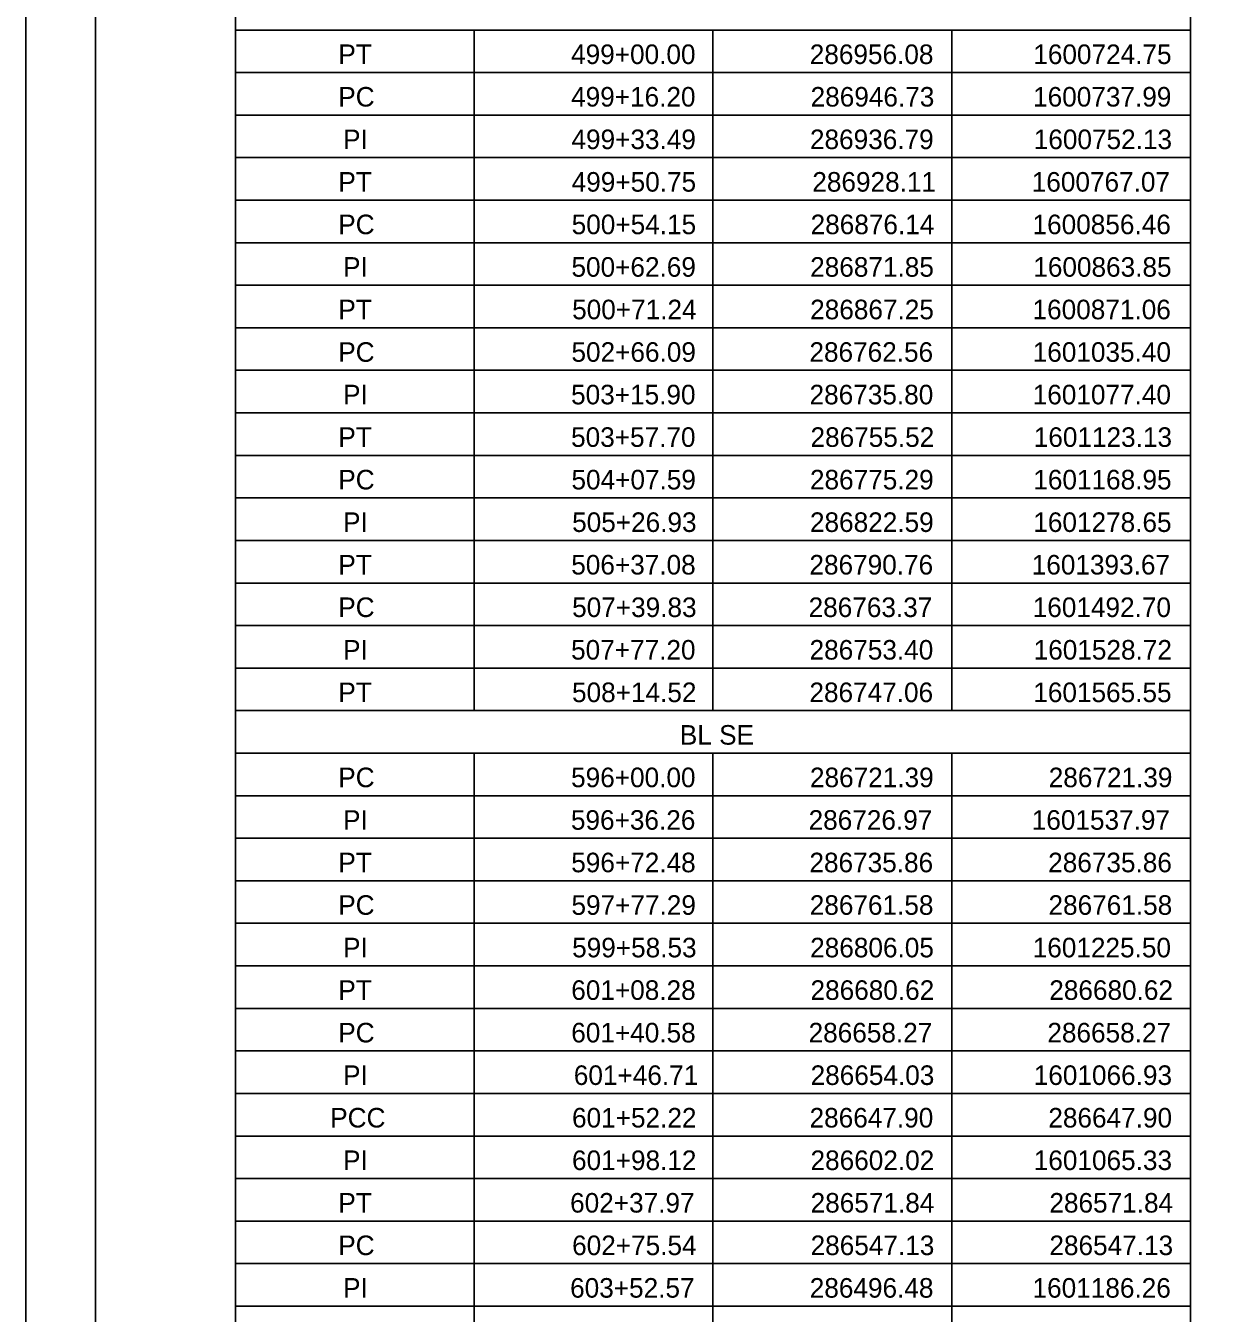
# Model space of a CAD drawing. Extents: x 0 to 34, y 0 to 22.
# Drawn here: x 0 to 8.5, y 7.75 to 16.97 of the extents above; entities that cross this region are included whole.
import ezdxf

# ---------------------------------------------------------------- set-up
doc = ezdxf.new("R2010")
doc.units = 0
for name, color, linetype in [('SH_Border', 7, 'Continuous'), ('SH_Cut_Line', 7, 'Continuous'), ('SH_Text', 7, 'Continuous')]:
    doc.layers.add(name, color=color, linetype=linetype)

msp = doc.modelspace()

# ---------------------------------------------------------------- linework, layer by layer
at = {"layer": 'SH_Border'}
for points in [[(0.5, 21.5), (1.5, 21.5), (1.5, 0.5), (0.5, 0.5)], [(1.5, 21.5), (33.5, 21.5), (33.5, 0.5), (1.5, 0.5)]]:
    msp.add_lwpolyline(points, close=True, dxfattribs=at)
at = {"layer": 'SH_Cut_Line'}
msp.add_lwpolyline([(0, 0), (34, 0), (34, 22), (0, 22)], close=True, dxfattribs=at)
at = {"layer": 'SH_Text'}
for p, q in [((1.5, 17.2391), (1.5, 16.3261)), ((8.3309, 17.2391), (8.3309, 16.3261)), ((1.5, 16.9348), (8.3309, 16.9348)), ((3.2077, 16.9348), (3.2077, 16.3261)), ((4.9155, 16.9348), (4.9155, 16.3261)), ((6.6232, 16.9348), (6.6232, 16.3261)), ((1.5, 16.6304), (8.3309, 16.6304)), ((1.5, 16.3261), (8.3309, 16.3261)), ((1.5, 16.3261), (1.5, 16.0217)), ((3.2077, 16.3261), (3.2077, 16.0217)), ((4.9155, 16.3261), (4.9155, 16.0217)), ((6.6232, 16.3261), (6.6232, 16.0217)), ((8.3309, 16.3261), (8.3309, 16.0217)), ((1.5, 16.0217), (8.3309, 16.0217)), ((1.5, 16.0217), (1.5, 15.413)), ((3.2077, 16.0217), (3.2077, 15.413)), ((4.9155, 16.0217), (4.9155, 15.413)), ((6.6232, 16.0217), (6.6232, 15.413)), ((8.3309, 16.0217), (8.3309, 15.413)), ((1.5, 15.7174), (8.3309, 15.7174)), ((1.5, 15.413), (8.3309, 15.413)), ((1.5, 15.413), (1.5, 15.1087)), ((3.2077, 15.413), (3.2077, 15.1087)), ((4.9155, 15.413), (4.9155, 15.1087)), ((6.6232, 15.413), (6.6232, 15.1087)), ((8.3309, 15.413), (8.3309, 15.1087)), ((1.5, 15.1087), (8.3309, 15.1087)), ((1.5, 15.1087), (1.5, 14.5)), ((3.2077, 15.1087), (3.2077, 14.5)), ((4.9155, 15.1087), (4.9155, 14.5)), ((6.6232, 15.1087), (6.6232, 14.5)), ((8.3309, 15.1087), (8.3309, 14.5)), ((1.5, 14.8043), (8.3309, 14.8043)), ((1.5, 14.5), (8.3309, 14.5)), ((1.5, 14.5), (1.5, 14.1957)), ((3.2077, 14.5), (3.2077, 14.1957)), ((4.9155, 14.5), (4.9155, 14.1957)), ((6.6232, 14.5), (6.6232, 14.1957)), ((8.3309, 14.5), (8.3309, 14.1957)), ((1.5, 14.1957), (8.3309, 14.1957)), ((1.5, 14.1957), (1.5, 13.587)), ((3.2077, 14.1957), (3.2077, 13.587)), ((4.9155, 14.1957), (4.9155, 13.587)), ((6.6232, 14.1957), (6.6232, 13.587)), ((8.3309, 14.1957), (8.3309, 13.587)), ((1.5, 13.8913), (8.3309, 13.8913)), ((1.5, 13.587), (8.3309, 13.587)), ((1.5, 13.587), (1.5, 13.2826)), ((3.2077, 13.587), (3.2077, 13.2826)), ((4.9155, 13.587), (4.9155, 13.2826)), ((6.6232, 13.587), (6.6232, 13.2826)), ((8.3309, 13.587), (8.3309, 13.2826)), ((1.5, 13.2826), (8.3309, 13.2826)), ((1.5, 13.2826), (1.5, 12.6739)), ((3.2077, 13.2826), (3.2077, 12.6739)), ((4.9155, 13.2826), (4.9155, 12.6739)), ((6.6232, 13.2826), (6.6232, 12.6739)), ((8.3309, 13.2826), (8.3309, 12.6739)), ((1.5, 12.9783), (8.3309, 12.9783)), ((1.5, 12.6739), (8.3309, 12.6739)), ((1.5, 12.6739), (1.5, 12.3696)), ((3.2077, 12.6739), (3.2077, 12.3696)), ((4.9155, 12.6739), (4.9155, 12.3696)), ((6.6232, 12.6739), (6.6232, 12.3696)), ((8.3309, 12.6739), (8.3309, 12.3696)), ((1.5, 12.3696), (8.3309, 12.3696)), ((1.5, 12.3696), (1.5, 11.4565)), ((3.2077, 12.3696), (3.2077, 12.0652)), ((4.9155, 12.3696), (4.9155, 12.0652)), ((6.6232, 12.3696), (6.6232, 12.0652)), ((8.3309, 12.3696), (8.3309, 11.4565)), ((1.5, 12.0652), (8.3309, 12.0652)), ((1.5, 11.7609), (8.3309, 11.7609)), ((3.2077, 11.7609), (3.2077, 11.4565)), ((4.9155, 11.7609), (4.9155, 11.4565)), ((6.6232, 11.7609), (6.6232, 11.4565)), ((1.5, 11.4565), (8.3309, 11.4565)), ((1.5, 11.4565), (1.5, 11.1522)), ((3.2077, 11.4565), (3.2077, 11.1522)), ((4.9155, 11.4565), (4.9155, 11.1522)), ((6.6232, 11.4565), (6.6232, 11.1522)), ((8.3309, 11.4565), (8.3309, 11.1522)), ((1.5, 11.1522), (8.3309, 11.1522)), ((1.5, 11.1522), (1.5, 10.5435)), ((3.2077, 11.1522), (3.2077, 10.5435)), ((4.9155, 11.1522), (4.9155, 10.5435)), ((6.6232, 11.1522), (6.6232, 10.5435)), ((8.3309, 11.1522), (8.3309, 10.5435)), ((1.5, 10.8478), (8.3309, 10.8478)), ((1.5, 10.5435), (8.3309, 10.5435)), ((1.5, 10.5435), (1.5, 10.2391)), ((3.2077, 10.5435), (3.2077, 10.2391)), ((4.9155, 10.5435), (4.9155, 10.2391)), ((6.6232, 10.5435), (6.6232, 10.2391)), ((8.3309, 10.5435), (8.3309, 10.2391)), ((1.5, 10.2391), (8.3309, 10.2391)), ((1.5, 10.2391), (1.5, 9.6304)), ((3.2077, 10.2391), (3.2077, 9.6304)), ((4.9155, 10.2391), (4.9155, 9.6304)), ((6.6232, 10.2391), (6.6232, 9.6304)), ((8.3309, 10.2391), (8.3309, 9.6304)), ((1.5, 9.9348), (8.3309, 9.9348)), ((1.5, 9.6304), (8.3309, 9.6304)), ((1.5, 9.6304), (1.5, 9.3261)), ((3.2077, 9.6304), (3.2077, 9.3261)), ((4.9155, 9.6304), (4.9155, 9.3261)), ((6.6232, 9.6304), (6.6232, 9.3261)), ((8.3309, 9.6304), (8.3309, 9.3261)), ((1.5, 9.3261), (8.3309, 9.3261)), ((1.5, 9.3261), (1.5, 9.0217)), ((3.2077, 9.3261), (3.2077, 9.0217)), ((4.9155, 9.3261), (4.9155, 9.0217)), ((6.6232, 9.3261), (6.6232, 9.0217)), ((8.3309, 9.3261), (8.3309, 9.0217)), ((1.5, 9.0217), (8.3309, 9.0217)), ((1.5, 9.0217), (1.5, 8.7174)), ((3.2077, 9.0217), (3.2077, 8.7174)), ((4.9155, 9.0217), (4.9155, 8.7174)), ((6.6232, 9.0217), (6.6232, 8.7174)), ((8.3309, 9.0217), (8.3309, 8.7174)), ((1.5, 8.7174), (8.3309, 8.7174)), ((1.5, 8.7174), (1.5, 8.1087)), ((3.2077, 8.7174), (3.2077, 8.1087)), ((4.9155, 8.7174), (4.9155, 8.1087)), ((6.6232, 8.7174), (6.6232, 8.1087)), ((8.3309, 8.7174), (8.3309, 8.1087)), ((1.5, 8.413), (8.3309, 8.413)), ((1.5, 8.1087), (8.3309, 8.1087)), ((1.5, 8.1087), (1.5, 7.8043)), ((3.2077, 8.1087), (3.2077, 7.8043)), ((4.9155, 8.1087), (4.9155, 7.8043)), ((6.6232, 8.1087), (6.6232, 7.8043)), ((8.3309, 8.1087), (8.3309, 7.8043)), ((1.5, 7.8043), (8.3309, 7.8043)), ((1.5, 7.8043), (1.5, 7.1957)), ((3.2077, 7.8043), (3.2077, 7.1957)), ((4.9155, 7.8043), (4.9155, 7.1957)), ((6.6232, 7.8043), (6.6232, 7.1957)), ((8.3309, 7.8043), (8.3309, 7.1957))]:
    msp.add_line(p, q, dxfattribs=at)
for points in [[(1.5, 16.9348), (3.2077, 16.9348), (3.2077, 16.6304), (1.5, 16.6304)], [(3.2077, 16.9348), (4.9155, 16.9348), (4.9155, 16.6304), (3.2077, 16.6304)], [(4.9155, 16.9348), (6.6232, 16.9348), (6.6232, 16.6304), (4.9155, 16.6304)], [(6.6232, 16.9348), (8.3309, 16.9348), (8.3309, 16.6304), (6.6232, 16.6304)], [(1.5, 16.6304), (3.2077, 16.6304), (3.2077, 16.3261), (1.5, 16.3261)], [(3.2077, 16.6304), (4.9155, 16.6304), (4.9155, 16.3261), (3.2077, 16.3261)], [(4.9155, 16.6304), (6.6232, 16.6304), (6.6232, 16.3261), (4.9155, 16.3261)], [(6.6232, 16.6304), (8.3309, 16.6304), (8.3309, 16.3261), (6.6232, 16.3261)], [(1.5, 16.3261), (3.2077, 16.3261), (3.2077, 16.0217), (1.5, 16.0217)], [(3.2077, 16.3261), (4.9155, 16.3261), (4.9155, 16.0217), (3.2077, 16.0217)], [(4.9155, 16.3261), (6.6232, 16.3261), (6.6232, 16.0217), (4.9155, 16.0217)], [(6.6232, 16.3261), (8.3309, 16.3261), (8.3309, 16.0217), (6.6232, 16.0217)], [(1.5, 16.0217), (3.2077, 16.0217), (3.2077, 15.7174), (1.5, 15.7174)], [(3.2077, 16.0217), (4.9155, 16.0217), (4.9155, 15.7174), (3.2077, 15.7174)], [(4.9155, 16.0217), (6.6232, 16.0217), (6.6232, 15.7174), (4.9155, 15.7174)], [(6.6232, 16.0217), (8.3309, 16.0217), (8.3309, 15.7174), (6.6232, 15.7174)], [(1.5, 15.7174), (3.2077, 15.7174), (3.2077, 15.413), (1.5, 15.413)], [(3.2077, 15.7174), (4.9155, 15.7174), (4.9155, 15.413), (3.2077, 15.413)], [(4.9155, 15.7174), (6.6232, 15.7174), (6.6232, 15.413), (4.9155, 15.413)], [(6.6232, 15.7174), (8.3309, 15.7174), (8.3309, 15.413), (6.6232, 15.413)], [(1.5, 15.413), (3.2077, 15.413), (3.2077, 15.1087), (1.5, 15.1087)], [(3.2077, 15.413), (4.9155, 15.413), (4.9155, 15.1087), (3.2077, 15.1087)], [(4.9155, 15.413), (6.6232, 15.413), (6.6232, 15.1087), (4.9155, 15.1087)], [(6.6232, 15.413), (8.3309, 15.413), (8.3309, 15.1087), (6.6232, 15.1087)], [(1.5, 15.1087), (3.2077, 15.1087), (3.2077, 14.8043), (1.5, 14.8043)], [(3.2077, 15.1087), (4.9155, 15.1087), (4.9155, 14.8043), (3.2077, 14.8043)], [(4.9155, 15.1087), (6.6232, 15.1087), (6.6232, 14.8043), (4.9155, 14.8043)], [(6.6232, 15.1087), (8.3309, 15.1087), (8.3309, 14.8043), (6.6232, 14.8043)], [(1.5, 14.8043), (3.2077, 14.8043), (3.2077, 14.5), (1.5, 14.5)], [(3.2077, 14.8043), (4.9155, 14.8043), (4.9155, 14.5), (3.2077, 14.5)], [(4.9155, 14.8043), (6.6232, 14.8043), (6.6232, 14.5), (4.9155, 14.5)], [(6.6232, 14.8043), (8.3309, 14.8043), (8.3309, 14.5), (6.6232, 14.5)], [(1.5, 14.5), (3.2077, 14.5), (3.2077, 14.1957), (1.5, 14.1957)], [(3.2077, 14.5), (4.9155, 14.5), (4.9155, 14.1957), (3.2077, 14.1957)], [(4.9155, 14.5), (6.6232, 14.5), (6.6232, 14.1957), (4.9155, 14.1957)], [(6.6232, 14.5), (8.3309, 14.5), (8.3309, 14.1957), (6.6232, 14.1957)], [(1.5, 14.1957), (3.2077, 14.1957), (3.2077, 13.8913), (1.5, 13.8913)], [(3.2077, 14.1957), (4.9155, 14.1957), (4.9155, 13.8913), (3.2077, 13.8913)], [(4.9155, 14.1957), (6.6232, 14.1957), (6.6232, 13.8913), (4.9155, 13.8913)], [(6.6232, 14.1957), (8.3309, 14.1957), (8.3309, 13.8913), (6.6232, 13.8913)], [(1.5, 13.8913), (3.2077, 13.8913), (3.2077, 13.587), (1.5, 13.587)], [(3.2077, 13.8913), (4.9155, 13.8913), (4.9155, 13.587), (3.2077, 13.587)], [(4.9155, 13.8913), (6.6232, 13.8913), (6.6232, 13.587), (4.9155, 13.587)], [(6.6232, 13.8913), (8.3309, 13.8913), (8.3309, 13.587), (6.6232, 13.587)], [(1.5, 13.587), (3.2077, 13.587), (3.2077, 13.2826), (1.5, 13.2826)], [(3.2077, 13.587), (4.9155, 13.587), (4.9155, 13.2826), (3.2077, 13.2826)], [(4.9155, 13.587), (6.6232, 13.587), (6.6232, 13.2826), (4.9155, 13.2826)], [(6.6232, 13.587), (8.3309, 13.587), (8.3309, 13.2826), (6.6232, 13.2826)], [(1.5, 13.2826), (3.2077, 13.2826), (3.2077, 12.9783), (1.5, 12.9783)], [(3.2077, 13.2826), (4.9155, 13.2826), (4.9155, 12.9783), (3.2077, 12.9783)], [(4.9155, 13.2826), (6.6232, 13.2826), (6.6232, 12.9783), (4.9155, 12.9783)], [(6.6232, 13.2826), (8.3309, 13.2826), (8.3309, 12.9783), (6.6232, 12.9783)], [(1.5, 12.9783), (3.2077, 12.9783), (3.2077, 12.6739), (1.5, 12.6739)], [(3.2077, 12.9783), (4.9155, 12.9783), (4.9155, 12.6739), (3.2077, 12.6739)], [(4.9155, 12.9783), (6.6232, 12.9783), (6.6232, 12.6739), (4.9155, 12.6739)], [(6.6232, 12.9783), (8.3309, 12.9783), (8.3309, 12.6739), (6.6232, 12.6739)], [(1.5, 12.6739), (3.2077, 12.6739), (3.2077, 12.3696), (1.5, 12.3696)], [(3.2077, 12.6739), (4.9155, 12.6739), (4.9155, 12.3696), (3.2077, 12.3696)], [(4.9155, 12.6739), (6.6232, 12.6739), (6.6232, 12.3696), (4.9155, 12.3696)], [(6.6232, 12.6739), (8.3309, 12.6739), (8.3309, 12.3696), (6.6232, 12.3696)], [(1.5, 12.3696), (3.2077, 12.3696), (3.2077, 12.0652), (1.5, 12.0652)], [(3.2077, 12.3696), (4.9155, 12.3696), (4.9155, 12.0652), (3.2077, 12.0652)], [(4.9155, 12.3696), (6.6232, 12.3696), (6.6232, 12.0652), (4.9155, 12.0652)], [(6.6232, 12.3696), (8.3309, 12.3696), (8.3309, 12.0652), (6.6232, 12.0652)], [(1.5, 11.7609), (3.2077, 11.7609), (3.2077, 11.4565), (1.5, 11.4565)], [(3.2077, 11.7609), (4.9155, 11.7609), (4.9155, 11.4565), (3.2077, 11.4565)], [(4.9155, 11.7609), (6.6232, 11.7609), (6.6232, 11.4565), (4.9155, 11.4565)], [(6.6232, 11.7609), (8.3309, 11.7609), (8.3309, 11.4565), (6.6232, 11.4565)], [(1.5, 11.4565), (3.2077, 11.4565), (3.2077, 11.1522), (1.5, 11.1522)], [(3.2077, 11.4565), (4.9155, 11.4565), (4.9155, 11.1522), (3.2077, 11.1522)], [(4.9155, 11.4565), (6.6232, 11.4565), (6.6232, 11.1522), (4.9155, 11.1522)], [(6.6232, 11.4565), (8.3309, 11.4565), (8.3309, 11.1522), (6.6232, 11.1522)], [(1.5, 11.1522), (3.2077, 11.1522), (3.2077, 10.8478), (1.5, 10.8478)], [(3.2077, 11.1522), (4.9155, 11.1522), (4.9155, 10.8478), (3.2077, 10.8478)], [(4.9155, 11.1522), (6.6232, 11.1522), (6.6232, 10.8478), (4.9155, 10.8478)], [(6.6232, 11.1522), (8.3309, 11.1522), (8.3309, 10.8478), (6.6232, 10.8478)], [(1.5, 10.8478), (3.2077, 10.8478), (3.2077, 10.5435), (1.5, 10.5435)], [(3.2077, 10.8478), (4.9155, 10.8478), (4.9155, 10.5435), (3.2077, 10.5435)], [(4.9155, 10.8478), (6.6232, 10.8478), (6.6232, 10.5435), (4.9155, 10.5435)], [(6.6232, 10.8478), (8.3309, 10.8478), (8.3309, 10.5435), (6.6232, 10.5435)], [(1.5, 10.5435), (3.2077, 10.5435), (3.2077, 10.2391), (1.5, 10.2391)], [(3.2077, 10.5435), (4.9155, 10.5435), (4.9155, 10.2391), (3.2077, 10.2391)], [(4.9155, 10.5435), (6.6232, 10.5435), (6.6232, 10.2391), (4.9155, 10.2391)], [(6.6232, 10.5435), (8.3309, 10.5435), (8.3309, 10.2391), (6.6232, 10.2391)], [(1.5, 10.2391), (3.2077, 10.2391), (3.2077, 9.9348), (1.5, 9.9348)], [(3.2077, 10.2391), (4.9155, 10.2391), (4.9155, 9.9348), (3.2077, 9.9348)], [(4.9155, 10.2391), (6.6232, 10.2391), (6.6232, 9.9348), (4.9155, 9.9348)], [(6.6232, 10.2391), (8.3309, 10.2391), (8.3309, 9.9348), (6.6232, 9.9348)], [(1.5, 9.9348), (3.2077, 9.9348), (3.2077, 9.6304), (1.5, 9.6304)], [(3.2077, 9.9348), (4.9155, 9.9348), (4.9155, 9.6304), (3.2077, 9.6304)], [(4.9155, 9.9348), (6.6232, 9.9348), (6.6232, 9.6304), (4.9155, 9.6304)], [(6.6232, 9.9348), (8.3309, 9.9348), (8.3309, 9.6304), (6.6232, 9.6304)], [(1.5, 9.6304), (3.2077, 9.6304), (3.2077, 9.3261), (1.5, 9.3261)], [(3.2077, 9.6304), (4.9155, 9.6304), (4.9155, 9.3261), (3.2077, 9.3261)], [(4.9155, 9.6304), (6.6232, 9.6304), (6.6232, 9.3261), (4.9155, 9.3261)], [(6.6232, 9.6304), (8.3309, 9.6304), (8.3309, 9.3261), (6.6232, 9.3261)], [(1.5, 9.3261), (3.2077, 9.3261), (3.2077, 9.0217), (1.5, 9.0217)], [(3.2077, 9.3261), (4.9155, 9.3261), (4.9155, 9.0217), (3.2077, 9.0217)], [(4.9155, 9.3261), (6.6232, 9.3261), (6.6232, 9.0217), (4.9155, 9.0217)], [(6.6232, 9.3261), (8.3309, 9.3261), (8.3309, 9.0217), (6.6232, 9.0217)], [(1.5, 9.0217), (3.2077, 9.0217), (3.2077, 8.7174), (1.5, 8.7174)], [(3.2077, 9.0217), (4.9155, 9.0217), (4.9155, 8.7174), (3.2077, 8.7174)], [(4.9155, 9.0217), (6.6232, 9.0217), (6.6232, 8.7174), (4.9155, 8.7174)], [(6.6232, 9.0217), (8.3309, 9.0217), (8.3309, 8.7174), (6.6232, 8.7174)], [(1.5, 8.7174), (3.2077, 8.7174), (3.2077, 8.413), (1.5, 8.413)], [(3.2077, 8.7174), (4.9155, 8.7174), (4.9155, 8.413), (3.2077, 8.413)], [(4.9155, 8.7174), (6.6232, 8.7174), (6.6232, 8.413), (4.9155, 8.413)], [(6.6232, 8.7174), (8.3309, 8.7174), (8.3309, 8.413), (6.6232, 8.413)], [(1.5, 8.413), (3.2077, 8.413), (3.2077, 8.1087), (1.5, 8.1087)], [(3.2077, 8.413), (4.9155, 8.413), (4.9155, 8.1087), (3.2077, 8.1087)], [(4.9155, 8.413), (6.6232, 8.413), (6.6232, 8.1087), (4.9155, 8.1087)], [(6.6232, 8.413), (8.3309, 8.413), (8.3309, 8.1087), (6.6232, 8.1087)], [(1.5, 8.1087), (3.2077, 8.1087), (3.2077, 7.8043), (1.5, 7.8043)], [(3.2077, 8.1087), (4.9155, 8.1087), (4.9155, 7.8043), (3.2077, 7.8043)], [(4.9155, 8.1087), (6.6232, 8.1087), (6.6232, 7.8043), (4.9155, 7.8043)], [(6.6232, 8.1087), (8.3309, 8.1087), (8.3309, 7.8043), (6.6232, 7.8043)], [(1.5, 7.8043), (3.2077, 7.8043), (3.2077, 7.5), (1.5, 7.5)], [(3.2077, 7.8043), (4.9155, 7.8043), (4.9155, 7.5), (3.2077, 7.5)], [(4.9155, 7.8043), (6.6232, 7.8043), (6.6232, 7.5), (4.9155, 7.5)], [(6.6232, 7.8043), (8.3309, 7.8043), (8.3309, 7.5), (6.6232, 7.5)]]:
    msp.add_lwpolyline(points, close=True, dxfattribs=at)

# ---------------------------------------------------------------- texts
for s, p in [('PT', (2.2359, 16.6913)), ('499+00.00', (3.9006, 16.6913)), ('286956.08', (5.6076, 16.6913)), ('1600724.75', (7.2066, 16.6913)), ('PC', (2.2352, 16.387)), ('499+16.20', (3.9006, 16.387)), ('286946.73', (5.6139, 16.387)), ('1600737.99', (7.2052, 16.387)), ('PI', (2.2696, 16.0826)), ('499+33.49', (3.9033, 16.0826)), ('286936.79', (5.6092, 16.0826)), ('1600752.13', (7.2099, 16.0826)), ('PT', (2.2359, 15.7783)), ('499+50.75', (3.9048, 15.7783)), ('286928.11', (5.626, 15.7783)), ('1600767.07', (7.1955, 15.7783)), ('PC', (2.2352, 15.4739)), ('500+54.15', (3.9048, 15.4739)), ('286876.14', (5.6139, 15.4739)), ('1600856.46', (7.2013, 15.4739)), ('PI', (2.2696, 15.1696)), ('500+62.69', (3.9033, 15.1696)), ('286871.85', (5.6107, 15.1696)), ('1600863.85', (7.2066, 15.1696)), ('PT', (2.2359, 14.8652)), ('500+71.24', (3.9081, 14.8652)), ('286867.25', (5.6107, 14.8652)), ('1600871.06', (7.2013, 14.8652)), ('PC', (2.2352, 14.5609)), ('502+66.09', (3.9033, 14.5609)), ('286762.56', (5.6053, 14.5609)), ('1601035.40', (7.2024, 14.5609)), ('PI', (2.2696, 14.2565)), ('503+15.90', (3.9006, 14.2565)), ('286735.80', (5.6064, 14.2565)), ('1601077.40', (7.2024, 14.2565)), ('503+57.70', (3.9006, 13.9522)), ('286755.52', (5.6132, 13.9522)), ('1601123.13', (7.2099, 13.9522)), ('PT', (2.2359, 13.9522)), ('PC', (2.2352, 13.6478)), ('504+07.59', (3.9033, 13.6478)), ('286775.29', (5.6092, 13.6478)), ('1601168.95', (7.2066, 13.6478)), ('PI', (2.2696, 13.3435)), ('505+26.93', (3.9081, 13.3435)), ('286822.59', (5.6092, 13.3435)), ('1601278.65', (7.2066, 13.3435)), ('PT', (2.2359, 13.0391)), ('506+37.08', (3.9017, 13.0391)), ('286790.76', (5.6053, 13.0391)), ('1601393.67', (7.1955, 13.0391)), ('PC', (2.2352, 12.7348)), ('507+39.83', (3.9081, 12.7348)), ('286763.37', (5.5995, 12.7348)), ('1601492.70', (7.2024, 12.7348)), ('PI', (2.2696, 12.4304)), ('507+77.20', (3.9006, 12.4304)), ('286753.40', (5.6064, 12.4304)), ('1601528.72', (7.2091, 12.4304)), ('PT', (2.2359, 12.1261)), ('508+14.52', (3.9073, 12.1261)), ('286747.06', (5.6053, 12.1261)), ('1601565.55', (7.2066, 12.1261)), ('BL SE', (4.6784, 11.8217)), ('PC', (2.2352, 11.5174)), ('596+00.00', (3.9006, 11.5174)), ('286721.39', (5.6092, 11.5174)), ('286721.39', (7.3169, 11.5174)), ('PI', (2.2696, 11.213)), ('596+36.26', (3.8994, 11.213)), ('286726.97', (5.5995, 11.213)), ('1601537.97', (7.1955, 11.213)), ('PT', (2.2359, 10.9087)), ('596+72.48', (3.9017, 10.9087)), ('286735.86', (5.6053, 10.9087)), ('286735.86', (7.313, 10.9087)), ('PC', (2.2352, 10.6043)), ('597+77.29', (3.9033, 10.6043)), ('286761.58', (5.6076, 10.6043)), ('286761.58', (7.3154, 10.6043)), ('PI', (2.2696, 10.3)), ('599+58.53', (3.9081, 10.3)), ('286806.05', (5.6107, 10.3)), ('1601225.50', (7.2024, 10.3)), ('PT', (2.2359, 9.9957)), ('601+08.28', (3.9017, 9.9957)), ('286680.62', (5.6132, 9.9957)), ('286680.62', (7.3209, 9.9957)), ('PC', (2.2352, 9.6913)), ('601+40.58', (3.9017, 9.6913)), ('286658.27', (5.5995, 9.6913)), ('286658.27', (7.3072, 9.6913)), ('PI', (2.2696, 9.387)), ('601+46.71', (3.9201, 9.387)), ('286654.03', (5.6139, 9.387)), ('1601066.93', (7.2099, 9.387)), ('PCC', (2.1776, 9.0826)), ('601+52.22', (3.9073, 9.0826)), ('286647.90', (5.6064, 9.0826)), ('286647.90', (7.3142, 9.0826)), ('PI', (2.2696, 8.7783)), ('601+98.12', (3.9073, 8.7783)), ('286602.02', (5.6132, 8.7783)), ('1601065.33', (7.2099, 8.7783)), ('PT', (2.2359, 8.4739)), ('602+37.97', (3.8936, 8.4739)), ('286571.84', (5.6139, 8.4739)), ('286571.84', (7.3217, 8.4739)), ('PC', (2.2352, 8.1696)), ('602+75.54', (3.9081, 8.1696)), ('286547.13', (5.6139, 8.1696)), ('286547.13', (7.3217, 8.1696)), ('PI', (2.2696, 7.8652)), ('603+52.57', (3.8936, 7.8652)), ('286496.48', (5.6076, 7.8652)), ('1601186.26', (7.2013, 7.8652))]:
    msp.add_text(s, height=0.14, dxfattribs=at).set_placement(p)

doc.saveas('drawing.dxf')
